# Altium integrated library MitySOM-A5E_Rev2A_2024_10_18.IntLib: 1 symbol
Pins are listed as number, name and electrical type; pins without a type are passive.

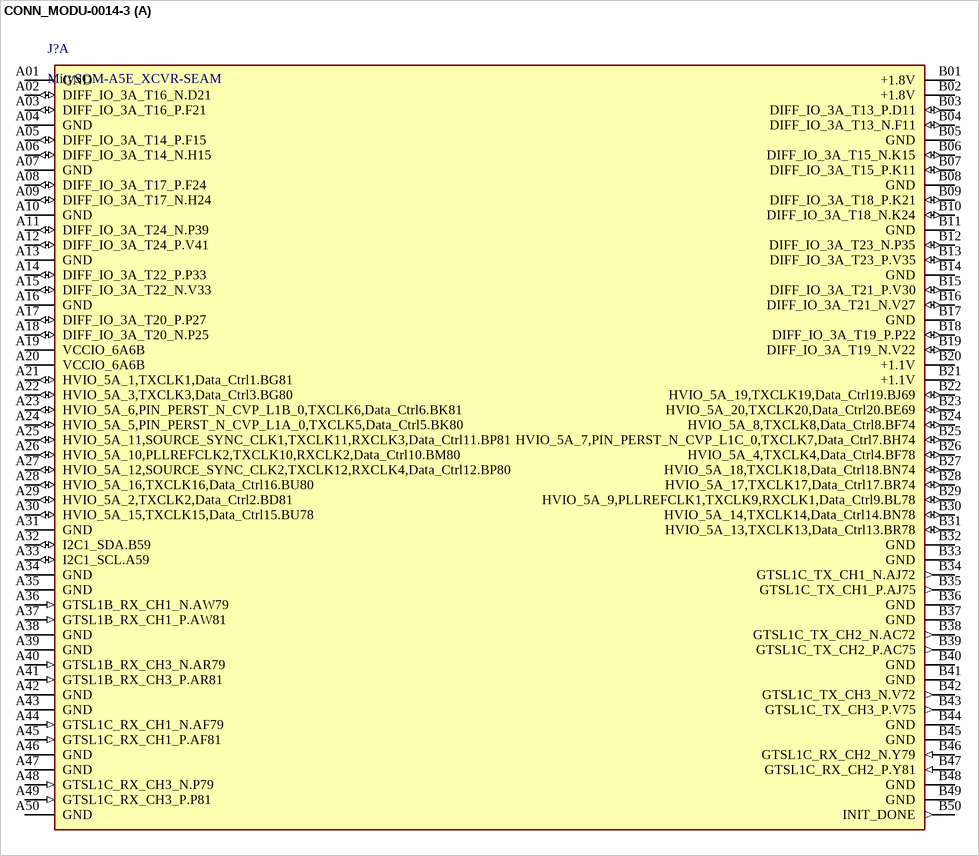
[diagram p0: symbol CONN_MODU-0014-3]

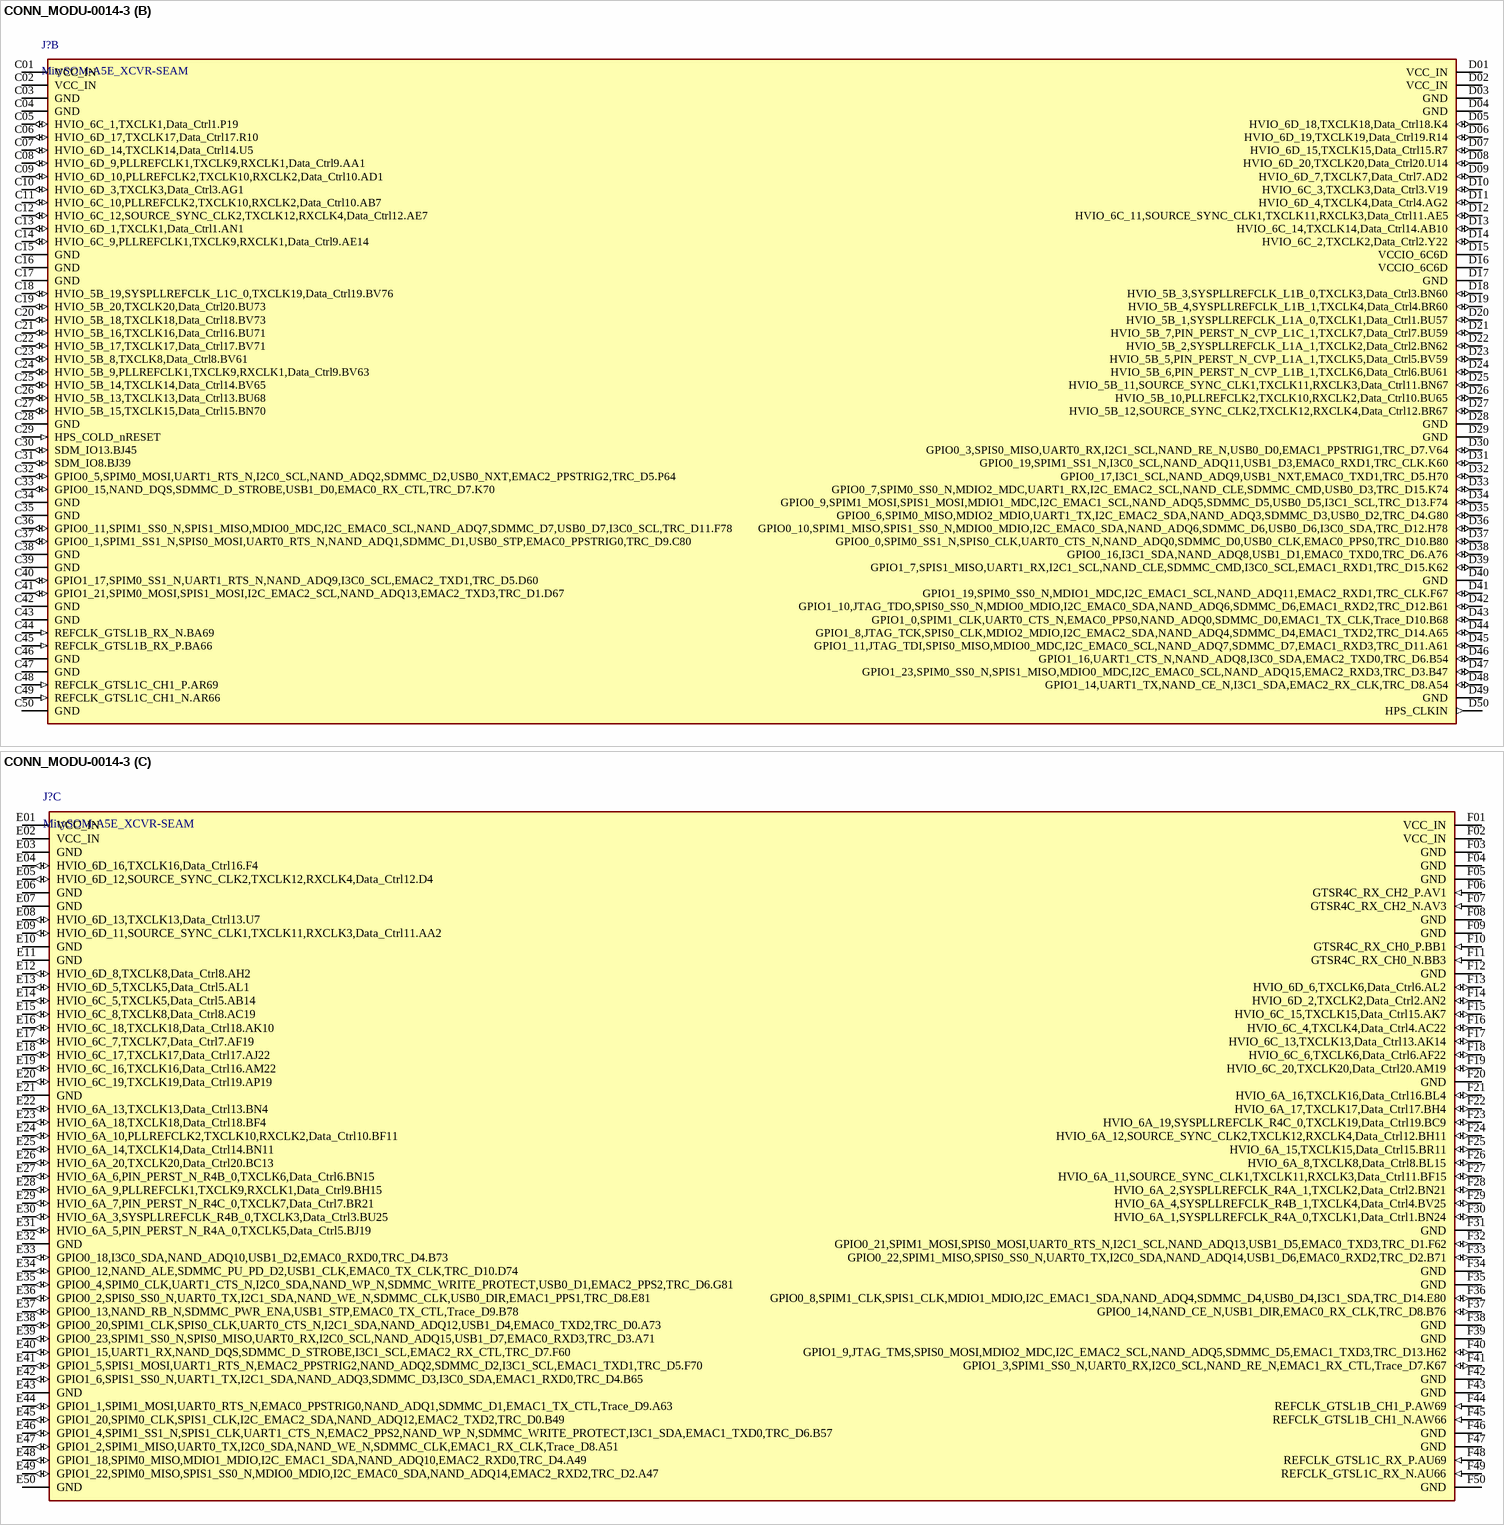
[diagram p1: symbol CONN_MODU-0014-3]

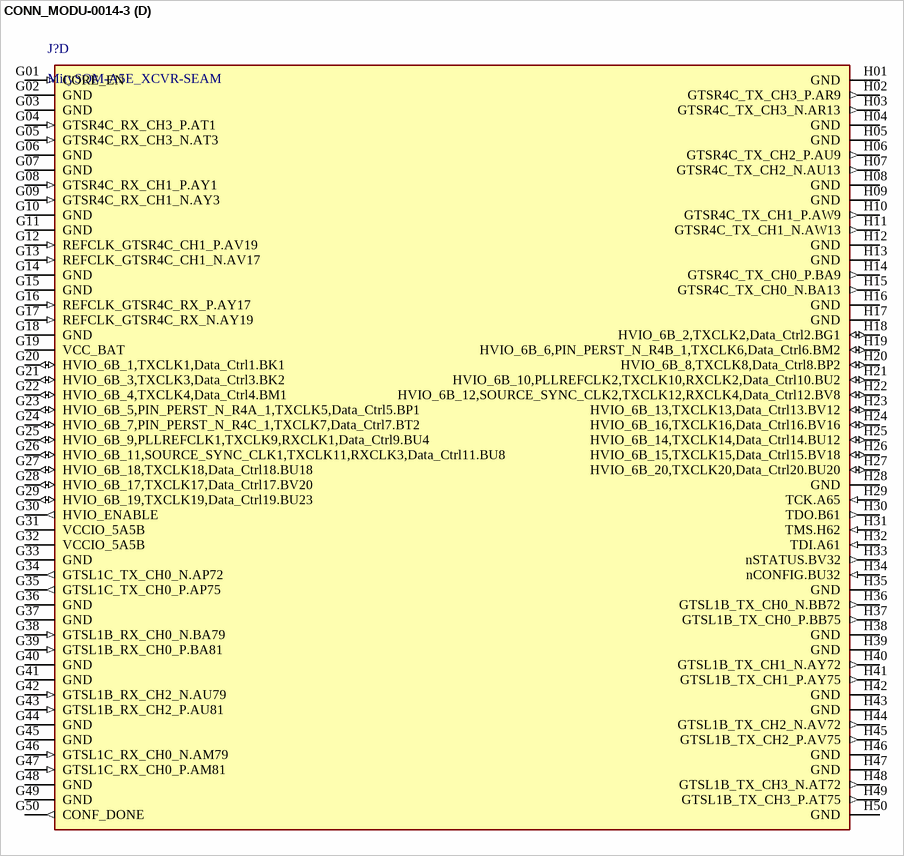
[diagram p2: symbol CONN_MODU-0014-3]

## CONN_MODU-0014-3
designator J?, comment MitySOM-A5E_XCVR-SEAM
MitySOM-A5E XCVR Interface Connector; Manuf 1_PN: SEAM-50-02.0-S-08-2-A-K-TR; Manuf 1: Samtec; CLPN: 13059; Angle: Vertical
footprint SEAM-50-02.0-S-08-2-A-K-TR (CONN ARRAY SOCKET 400 POS SMD)
part A pins: A01 GND (power), A02 DIFF_IO_3A_T16_N.D21 (io), A03 DIFF_IO_3A_T16_P.F21 (io), A04 GND (power), A05 DIFF_IO_3A_T14_P.F15 (io), A06 DIFF_IO_3A_T14_N.H15 (io), A07 GND (power), A08 DIFF_IO_3A_T17_P.F24 (io), A09 DIFF_IO_3A_T17_N.H24 (io), A10 GND (power), A11 DIFF_IO_3A_T24_N.P39 (io), A12 DIFF_IO_3A_T24_P.V41 (io), A13 GND (power), A14 DIFF_IO_3A_T22_P.P33 (io), A15 DIFF_IO_3A_T22_N.V33 (io), A16 GND (power), A17 DIFF_IO_3A_T20_P.P27 (io), A18 DIFF_IO_3A_T20_N.P25 (io), A19 VCCIO_6A6B (power), A20 VCCIO_6A6B (power), A21 HVIO_5A_1,TXCLK1,Data_Ctrl1.BG81 (io), A22 HVIO_5A_3,TXCLK3,Data_Ctrl3.BG80 (io), A23 HVIO_5A_6,PIN_PERST_N_CVP_L1B_0,TXCLK6,Data_Ctrl6.BK81 (io), A24 HVIO_5A_5,PIN_PERST_N_CVP_L1A_0,TXCLK5,Data_Ctrl5.BK80 (io), A25 HVIO_5A_11,SOURCE_SYNC_CLK1,TXCLK11,RXCLK3,Data_Ctrl11.BP81 (io), A26 HVIO_5A_10,PLLREFCLK2,TXCLK10,RXCLK2,Data_Ctrl10.BM80 (io), A27 HVIO_5A_12,SOURCE_SYNC_CLK2,TXCLK12,RXCLK4,Data_Ctrl12.BP80 (io), A28 HVIO_5A_16,TXCLK16,Data_Ctrl16.BU80 (io), A29 HVIO_5A_2,TXCLK2,Data_Ctrl2.BD81 (io), A30 HVIO_5A_15,TXCLK15,Data_Ctrl15.BU78 (io), A31 GND (power), A32 I2C1_SDA.B59 (io), A33 I2C1_SCL.A59 (io), A34 GND (power), A35 GND (power), A36 GTSL1B_RX_CH1_N.AW79 (in), A37 GTSL1B_RX_CH1_P.AW81 (in), A38 GND (power), A39 GND (power), A40 GTSL1B_RX_CH3_N.AR79 (in), A41 GTSL1B_RX_CH3_P.AR81 (in), A42 GND (power), A43 GND (power), A44 GTSL1C_RX_CH1_N.AF79 (in), A45 GTSL1C_RX_CH1_P.AF81 (in), A46 GND (power), A47 GND (power), A48 GTSL1C_RX_CH3_N.P79 (in), A49 GTSL1C_RX_CH3_P.P81 (in), A50 GND (power), B01 +1.8V (power), B02 +1.8V (power), B03 DIFF_IO_3A_T13_P.D11 (io), B04 DIFF_IO_3A_T13_N.F11 (io), B05 GND (power), B06 DIFF_IO_3A_T15_N.K15 (io), B07 DIFF_IO_3A_T15_P.K11 (io), B08 GND (power), B09 DIFF_IO_3A_T18_P.K21 (io), B10 DIFF_IO_3A_T18_N.K24 (io), B11 GND (power), B12 DIFF_IO_3A_T23_N.P35 (io), B13 DIFF_IO_3A_T23_P.V35 (io), B14 GND (power), B15 DIFF_IO_3A_T21_P.V30 (io), B16 DIFF_IO_3A_T21_N.V27 (io), B17 GND (power), B18 DIFF_IO_3A_T19_P.P22 (io), B19 DIFF_IO_3A_T19_N.V22 (io), B20 +1.1V (power), B21 +1.1V (power), B22 HVIO_5A_19,TXCLK19,Data_Ctrl19.BJ69 (io), B23 HVIO_5A_20,TXCLK20,Data_Ctrl20.BE69 (io), B24 HVIO_5A_8,TXCLK8,Data_Ctrl8.BF74 (io), B25 HVIO_5A_7,PIN_PERST_N_CVP_L1C_0,TXCLK7,Data_Ctrl7.BH74 (io), B26 HVIO_5A_4,TXCLK4,Data_Ctrl4.BF78 (io), B27 HVIO_5A_18,TXCLK18,Data_Ctrl18.BN74 (io), B28 HVIO_5A_17,TXCLK17,Data_Ctrl17.BR74 (io), B29 HVIO_5A_9,PLLREFCLK1,TXCLK9,RXCLK1,Data_Ctrl9.BL78 (io), B30 HVIO_5A_14,TXCLK14,Data_Ctrl14.BN78 (io), B31 HVIO_5A_13,TXCLK13,Data_Ctrl13.BR78 (io), B32 GND (power), B33 GND (power), B34 GTSL1C_TX_CH1_N.AJ72 (out), B35 GTSL1C_TX_CH1_P.AJ75 (out), B36 GND (power), B37 GND (power), B38 GTSL1C_TX_CH2_N.AC72 (out), B39 GTSL1C_TX_CH2_P.AC75 (out), B40 GND (power), B41 GND (power), B42 GTSL1C_TX_CH3_N.V72 (out), B43 GTSL1C_TX_CH3_P.V75 (out), B44 GND (power), B45 GND (power), B46 GTSL1C_RX_CH2_N.Y79 (in), B47 GTSL1C_RX_CH2_P.Y81 (in), B48 GND (power), B49 GND (power), B50 INIT_DONE (out)
part B pins: C01 VCC_IN (power), C02 VCC_IN (power), C03 GND (power), C04 GND (power), C05 HVIO_6C_1,TXCLK1,Data_Ctrl1.P19 (io), C06 HVIO_6D_17,TXCLK17,Data_Ctrl17.R10 (io), C07 HVIO_6D_14,TXCLK14,Data_Ctrl14.U5 (io), C08 HVIO_6D_9,PLLREFCLK1,TXCLK9,RXCLK1,Data_Ctrl9.AA1 (io), C09 HVIO_6D_10,PLLREFCLK2,TXCLK10,RXCLK2,Data_Ctrl10.AD1 (io), C10 HVIO_6D_3,TXCLK3,Data_Ctrl3.AG1 (io), C11 HVIO_6C_10,PLLREFCLK2,TXCLK10,RXCLK2,Data_Ctrl10.AB7 (io), C12 HVIO_6C_12,SOURCE_SYNC_CLK2,TXCLK12,RXCLK4,Data_Ctrl12.AE7 (io), C13 HVIO_6D_1,TXCLK1,Data_Ctrl1.AN1 (io), C14 HVIO_6C_9,PLLREFCLK1,TXCLK9,RXCLK1,Data_Ctrl9.AE14 (io), C15 GND (power), C16 GND (power), C17 GND (power), C18 HVIO_5B_19,SYSPLLREFCLK_L1C_0,TXCLK19,Data_Ctrl19.BV76 (io), C19 HVIO_5B_20,TXCLK20,Data_Ctrl20.BU73 (io), C20 HVIO_5B_18,TXCLK18,Data_Ctrl18.BV73 (io), C21 HVIO_5B_16,TXCLK16,Data_Ctrl16.BU71 (io), C22 HVIO_5B_17,TXCLK17,Data_Ctrl17.BV71 (io), C23 HVIO_5B_8,TXCLK8,Data_Ctrl8.BV61 (io), C24 HVIO_5B_9,PLLREFCLK1,TXCLK9,RXCLK1,Data_Ctrl9.BV63 (io), C25 HVIO_5B_14,TXCLK14,Data_Ctrl14.BV65 (io), C26 HVIO_5B_13,TXCLK13,Data_Ctrl13.BU68 (io), C27 HVIO_5B_15,TXCLK15,Data_Ctrl15.BN70 (io), C28 GND (power), C29 HPS_COLD_nRESET (in), C30 SDM_IO13.BJ45 (io), C31 SDM_IO8.BJ39 (io), C32 GPIO0_5,SPIM0_MOSI,UART1_RTS_N,I2C0_SCL,NAND_ADQ2,SDMMC_D2,USB0_NXT,EMAC2_PPSTRIG2,TRC_D5.P64 (io), C33 GPIO0_15,NAND_DQS,SDMMC_D_STROBE,USB1_D0,EMAC0_RX_CTL,TRC_D7.K70 (io), C34 GND (power), C35 GND (power), C36 GPIO0_11,SPIM1_SS0_N,SPIS1_MISO,MDIO0_MDC,I2C_EMAC0_SCL,NAND_ADQ7,SDMMC_D7,USB0_D7,I3C0_SCL,TRC_D11.F78 (io), C37 GPIO0_1,SPIM1_SS1_N,SPIS0_MOSI,UART0_RTS_N,NAND_ADQ1,SDMMC_D1,USB0_STP,EMAC0_PPSTRIG0,TRC_D9.C80 (io), C38 GND (power), C39 GND (power), C40 GPIO1_17,SPIM0_SS1_N,UART1_RTS_N,NAND_ADQ9,I3C0_SCL,EMAC2_TXD1,TRC_D5.D60 (io), C41 GPIO1_21,SPIM0_MOSI,SPIS1_MOSI,I2C_EMAC2_SCL,NAND_ADQ13,EMAC2_TXD3,TRC_D1.D67 (io), C42 GND (power), C43 GND (power), C44 REFCLK_GTSL1B_RX_N.BA69 (in), C45 REFCLK_GTSL1B_RX_P.BA66 (in), C46 GND (power), C47 GND (power), C48 REFCLK_GTSL1C_CH1_P.AR69 (in), C49 REFCLK_GTSL1C_CH1_N.AR66 (in), C50 GND (power), D01 VCC_IN (power), D02 VCC_IN (power), D03 GND (power), D04 GND (power), D05 HVIO_6D_18,TXCLK18,Data_Ctrl18.K4 (io), D06 HVIO_6D_19,TXCLK19,Data_Ctrl19.R14 (io), D07 HVIO_6D_15,TXCLK15,Data_Ctrl15.R7 (io), D08 HVIO_6D_20,TXCLK20,Data_Ctrl20.U14 (io), D09 HVIO_6D_7,TXCLK7,Data_Ctrl7.AD2 (io), D10 HVIO_6C_3,TXCLK3,Data_Ctrl3.V19 (io), D11 HVIO_6D_4,TXCLK4,Data_Ctrl4.AG2 (io), D12 HVIO_6C_11,SOURCE_SYNC_CLK1,TXCLK11,RXCLK3,Data_Ctrl11.AE5 (io), D13 HVIO_6C_14,TXCLK14,Data_Ctrl14.AB10 (io), D14 HVIO_6C_2,TXCLK2,Data_Ctrl2.Y22 (io), D15 VCCIO_6C6D (power), D16 VCCIO_6C6D (power), D17 GND (power), D18 HVIO_5B_3,SYSPLLREFCLK_L1B_0,TXCLK3,Data_Ctrl3.BN60 (io), D19 HVIO_5B_4,SYSPLLREFCLK_L1B_1,TXCLK4,Data_Ctrl4.BR60 (io), D20 HVIO_5B_1,SYSPLLREFCLK_L1A_0,TXCLK1,Data_Ctrl1.BU57 (io), D21 HVIO_5B_7,PIN_PERST_N_CVP_L1C_1,TXCLK7,Data_Ctrl7.BU59 (io), D22 HVIO_5B_2,SYSPLLREFCLK_L1A_1,TXCLK2,Data_Ctrl2.BN62 (io), D23 HVIO_5B_5,PIN_PERST_N_CVP_L1A_1,TXCLK5,Data_Ctrl5.BV59 (io), D24 HVIO_5B_6,PIN_PERST_N_CVP_L1B_1,TXCLK6,Data_Ctrl6.BU61 (io), D25 HVIO_5B_11,SOURCE_SYNC_CLK1,TXCLK11,RXCLK3,Data_Ctrl11.BN67 (io), D26 HVIO_5B_10,PLLREFCLK2,TXCLK10,RXCLK2,Data_Ctrl10.BU65 (io), D27 HVIO_5B_12,SOURCE_SYNC_CLK2,TXCLK12,RXCLK4,Data_Ctrl12.BR67 (io), D28 GND (power), D29 GND (power), D30 GPIO0_3,SPIS0_MISO,UART0_RX,I2C1_SCL,NAND_RE_N,USB0_D0,EMAC1_PPSTRIG1,TRC_D7.V64 (io), D31 GPIO0_19,SPIM1_SS1_N,I3C0_SCL,NAND_ADQ11,USB1_D3,EMAC0_RXD1,TRC_CLK.K60 (io), D32 GPIO0_17,I3C1_SCL,NAND_ADQ9,USB1_NXT,EMAC0_TXD1,TRC_D5.H70 (io), D33 GPIO0_7,SPIM0_SS0_N,MDIO2_MDC,UART1_RX,I2C_EMAC2_SCL,NAND_CLE,SDMMC_CMD,USB0_D3,TRC_D15.K74 (io), D34 GPIO0_9,SPIM1_MOSI,SPIS1_MOSI,MDIO1_MDC,I2C_EMAC1_SCL,NAND_ADQ5,SDMMC_D5,USB0_D5,I3C1_SCL,TRC_D13.F74 (io), D35 GPIO0_6,SPIM0_MISO,MDIO2_MDIO,UART1_TX,I2C_EMAC2_SDA,NAND_ADQ3,SDMMC_D3,USB0_D2,TRC_D4.G80 (io), D36 GPIO0_10,SPIM1_MISO,SPIS1_SS0_N,MDIO0_MDIO,I2C_EMAC0_SDA,NAND_ADQ6,SDMMC_D6,USB0_D6,I3C0_SDA,TRC_D12.H78 (io), D37 GPIO0_0,SPIM0_SS1_N,SPIS0_CLK,UART0_CTS_N,NAND_ADQ0,SDMMC_D0,USB0_CLK,EMAC0_PPS0,TRC_D10.B80 (io), D38 GPIO0_16,I3C1_SDA,NAND_ADQ8,USB1_D1,EMAC0_TXD0,TRC_D6.A76 (io), D39 GPIO1_7,SPIS1_MISO,UART1_RX,I2C1_SCL,NAND_CLE,SDMMC_CMD,I3C0_SCL,EMAC1_RXD1,TRC_D15.K62 (io), D40 GND (power), D41 GPIO1_19,SPIM0_SS0_N,MDIO1_MDC,I2C_EMAC1_SCL,NAND_ADQ11,EMAC2_RXD1,TRC_CLK.F67 (io), D42 GPIO1_10,JTAG_TDO,SPIS0_SS0_N,MDIO0_MDIO,I2C_EMAC0_SDA,NAND_ADQ6,SDMMC_D6,EMAC1_RXD2,TRC_D12.B61 (io), D43 GPIO1_0,SPIM1_CLK,UART0_CTS_N,EMAC0_PPS0,NAND_ADQ0,SDMMC_D0,EMAC1_TX_CLK,Trace_D10.B68 (io), D44 GPIO1_8,JTAG_TCK,SPIS0_CLK,MDIO2_MDIO,I2C_EMAC2_SDA,NAND_ADQ4,SDMMC_D4,EMAC1_TXD2,TRC_D14.A65 (io), D45 GPIO1_11,JTAG_TDI,SPIS0_MISO,MDIO0_MDC,I2C_EMAC0_SCL,NAND_ADQ7,SDMMC_D7,EMAC1_RXD3,TRC_D11.A61 (io), D46 GPIO1_16,UART1_CTS_N,NAND_ADQ8,I3C0_SDA,EMAC2_TXD0,TRC_D6.B54 (io), D47 GPIO1_23,SPIM0_SS0_N,SPIS1_MISO,MDIO0_MDC,I2C_EMAC0_SCL,NAND_ADQ15,EMAC2_RXD3,TRC_D3.B47 (io), D48 GPIO1_14,UART1_TX,NAND_CE_N,I3C1_SDA,EMAC2_RX_CLK,TRC_D8.A54 (io), D49 GND (power), D50 HPS_CLKIN (out)
part C pins: E01 VCC_IN (power), E02 VCC_IN (power), E03 GND (power), E04 HVIO_6D_16,TXCLK16,Data_Ctrl16.F4 (io), E05 HVIO_6D_12,SOURCE_SYNC_CLK2,TXCLK12,RXCLK4,Data_Ctrl12.D4 (io), E06 GND (power), E07 GND (power), E08 HVIO_6D_13,TXCLK13,Data_Ctrl13.U7 (io), E09 HVIO_6D_11,SOURCE_SYNC_CLK1,TXCLK11,RXCLK3,Data_Ctrl11.AA2 (io), E10 GND (power), E11 GND (power), E12 HVIO_6D_8,TXCLK8,Data_Ctrl8.AH2 (io), E13 HVIO_6D_5,TXCLK5,Data_Ctrl5.AL1 (io), E14 HVIO_6C_5,TXCLK5,Data_Ctrl5.AB14 (io), E15 HVIO_6C_8,TXCLK8,Data_Ctrl8.AC19 (io), E16 HVIO_6C_18,TXCLK18,Data_Ctrl18.AK10 (io), E17 HVIO_6C_7,TXCLK7,Data_Ctrl7.AF19 (io), E18 HVIO_6C_17,TXCLK17,Data_Ctrl17.AJ22 (io), E19 HVIO_6C_16,TXCLK16,Data_Ctrl16.AM22 (io), E20 HVIO_6C_19,TXCLK19,Data_Ctrl19.AP19 (io), E21 GND (power), E22 HVIO_6A_13,TXCLK13,Data_Ctrl13.BN4 (io), E23 HVIO_6A_18,TXCLK18,Data_Ctrl18.BF4 (io), E24 HVIO_6A_10,PLLREFCLK2,TXCLK10,RXCLK2,Data_Ctrl10.BF11 (io), E25 HVIO_6A_14,TXCLK14,Data_Ctrl14.BN11 (io), E26 HVIO_6A_20,TXCLK20,Data_Ctrl20.BC13 (io), E27 HVIO_6A_6,PIN_PERST_N_R4B_0,TXCLK6,Data_Ctrl6.BN15 (io), E28 HVIO_6A_9,PLLREFCLK1,TXCLK9,RXCLK1,Data_Ctrl9.BH15 (io), E29 HVIO_6A_7,PIN_PERST_N_R4C_0,TXCLK7,Data_Ctrl7.BR21 (io), E30 HVIO_6A_3,SYSPLLREFCLK_R4B_0,TXCLK3,Data_Ctrl3.BU25 (io), E31 HVIO_6A_5,PIN_PERST_N_R4A_0,TXCLK5,Data_Ctrl5.BJ19 (io), E32 GND (power), E33 GPIO0_18,I3C0_SDA,NAND_ADQ10,USB1_D2,EMAC0_RXD0,TRC_D4.B73 (io), E34 GPIO0_12,NAND_ALE,SDMMC_PU_PD_D2,USB1_CLK,EMAC0_TX_CLK,TRC_D10.D74 (io), E35 GPIO0_4,SPIM0_CLK,UART1_CTS_N,I2C0_SDA,NAND_WP_N,SDMMC_WRITE_PROTECT,USB0_D1,EMAC2_PPS2,TRC_D6.G81 (io), E36 GPIO0_2,SPIS0_SS0_N,UART0_TX,I2C1_SDA,NAND_WE_N,SDMMC_CLK,USB0_DIR,EMAC1_PPS1,TRC_D8.E81 (io), E37 GPIO0_13,NAND_RB_N,SDMMC_PWR_ENA,USB1_STP,EMAC0_TX_CTL,Trace_D9.B78 (io), E38 GPIO0_20,SPIM1_CLK,SPIS0_CLK,UART0_CTS_N,I2C1_SDA,NAND_ADQ12,USB1_D4,EMAC0_TXD2,TRC_D0.A73 (io), E39 GPIO0_23,SPIM1_SS0_N,SPIS0_MISO,UART0_RX,I2C0_SCL,NAND_ADQ15,USB1_D7,EMAC0_RXD3,TRC_D3.A71 (io), E40 GPIO1_15,UART1_RX,NAND_DQS,SDMMC_D_STROBE,I3C1_SCL,EMAC2_RX_CTL,TRC_D7.F60 (io), E41 GPIO1_5,SPIS1_MOSI,UART1_RTS_N,EMAC2_PPSTRIG2,NAND_ADQ2,SDMMC_D2,I3C1_SCL,EMAC1_TXD1,TRC_D5.F70 (io), E42 GPIO1_6,SPIS1_SS0_N,UART1_TX,I2C1_SDA,NAND_ADQ3,SDMMC_D3,I3C0_SDA,EMAC1_RXD0,TRC_D4.B65 (io), E43 GND (power), E44 GPIO1_1,SPIM1_MOSI,UART0_RTS_N,EMAC0_PPSTRIG0,NAND_ADQ1,SDMMC_D1,EMAC1_TX_CTL,Trace_D9.A63 (io), E45 GPIO1_20,SPIM0_CLK,SPIS1_CLK,I2C_EMAC2_SDA,NAND_ADQ12,EMAC2_TXD2,TRC_D0.B49 (io), E46 GPIO1_4,SPIM1_SS1_N,SPIS1_CLK,UART1_CTS_N,EMAC2_PPS2,NAND_WP_N,SDMMC_WRITE_PROTECT,I3C1_SDA,EMAC1_TXD0,TRC_D6.B57 (io), E47 GPIO1_2,SPIM1_MISO,UART0_TX,I2C0_SDA,NAND_WE_N,SDMMC_CLK,EMAC1_RX_CLK,Trace_D8.A51 (io), E48 GPIO1_18,SPIM0_MISO,MDIO1_MDIO,I2C_EMAC1_SDA,NAND_ADQ10,EMAC2_RXD0,TRC_D4.A49 (io), E49 GPIO1_22,SPIM0_MISO,SPIS1_SS0_N,MDIO0_MDIO,I2C_EMAC0_SDA,NAND_ADQ14,EMAC2_RXD2,TRC_D2.A47 (io), E50 GND (power), F01 VCC_IN (power), F02 VCC_IN (power), F03 GND (power), F04 GND (power), F05 GND (power), F06 GTSR4C_RX_CH2_P.AV1 (in), F07 GTSR4C_RX_CH2_N.AV3 (in), F08 GND (power), F09 GND (power), F10 GTSR4C_RX_CH0_P.BB1 (in), F11 GTSR4C_RX_CH0_N.BB3 (in), F12 GND (power), F13 HVIO_6D_6,TXCLK6,Data_Ctrl6.AL2 (io), F14 HVIO_6D_2,TXCLK2,Data_Ctrl2.AN2 (io), F15 HVIO_6C_15,TXCLK15,Data_Ctrl15.AK7 (io), F16 HVIO_6C_4,TXCLK4,Data_Ctrl4.AC22 (io), F17 HVIO_6C_13,TXCLK13,Data_Ctrl13.AK14 (io), F18 HVIO_6C_6,TXCLK6,Data_Ctrl6.AF22 (io), F19 HVIO_6C_20,TXCLK20,Data_Ctrl20.AM19 (io), F20 GND (power), F21 HVIO_6A_16,TXCLK16,Data_Ctrl16.BL4 (io), F22 HVIO_6A_17,TXCLK17,Data_Ctrl17.BH4 (io), F23 HVIO_6A_19,SYSPLLREFCLK_R4C_0,TXCLK19,Data_Ctrl19.BC9 (io), F24 HVIO_6A_12,SOURCE_SYNC_CLK2,TXCLK12,RXCLK4,Data_Ctrl12.BH11 (io), F25 HVIO_6A_15,TXCLK15,Data_Ctrl15.BR11 (io), F26 HVIO_6A_8,TXCLK8,Data_Ctrl8.BL15 (io), F27 HVIO_6A_11,SOURCE_SYNC_CLK1,TXCLK11,RXCLK3,Data_Ctrl11.BF15 (io), F28 HVIO_6A_2,SYSPLLREFCLK_R4A_1,TXCLK2,Data_Ctrl2.BN21 (io), F29 HVIO_6A_4,SYSPLLREFCLK_R4B_1,TXCLK4,Data_Ctrl4.BV25 (io), F30 HVIO_6A_1,SYSPLLREFCLK_R4A_0,TXCLK1,Data_Ctrl1.BN24 (io), F31 GND (power), F32 GPIO0_21,SPIM1_MOSI,SPIS0_MOSI,UART0_RTS_N,I2C1_SCL,NAND_ADQ13,USB1_D5,EMAC0_TXD3,TRC_D1.F62 (io), F33 GPIO0_22,SPIM1_MISO,SPIS0_SS0_N,UART0_TX,I2C0_SDA,NAND_ADQ14,USB1_D6,EMAC0_RXD2,TRC_D2.B71 (io), F34 GND (power), F35 GND (power), F36 GPIO0_8,SPIM1_CLK,SPIS1_CLK,MDIO1_MDIO,I2C_EMAC1_SDA,NAND_ADQ4,SDMMC_D4,USB0_D4,I3C1_SDA,TRC_D14.E80 (io), F37 GPIO0_14,NAND_CE_N,USB1_DIR,EMAC0_RX_CLK,TRC_D8.B76 (io), F38 GND (power), F39 GND (power), F40 GPIO1_9,JTAG_TMS,SPIS0_MOSI,MDIO2_MDC,I2C_EMAC2_SCL,NAND_ADQ5,SDMMC_D5,EMAC1_TXD3,TRC_D13.H62 (io), F41 GPIO1_3,SPIM1_SS0_N,UART0_RX,I2C0_SCL,NAND_RE_N,EMAC1_RX_CTL,Trace_D7.K67 (io), F42 GND (power), F43 GND (power), F44 REFCLK_GTSL1B_CH1_P.AW69 (in), F45 REFCLK_GTSL1B_CH1_N.AW66 (in), F46 GND (power), F47 GND (power), F48 REFCLK_GTSL1C_RX_P.AU69 (in), F49 REFCLK_GTSL1C_RX_N.AU66 (in), F50 GND (power)
part D pins: G01 CORE_EN (in), G02 GND (power), G03 GND (power), G04 GTSR4C_RX_CH3_P.AT1 (in), G05 GTSR4C_RX_CH3_N.AT3 (in), G06 GND (power), G07 GND (power), G08 GTSR4C_RX_CH1_P.AY1 (in), G09 GTSR4C_RX_CH1_N.AY3 (in), G10 GND (power), G11 GND (power), G12 REFCLK_GTSR4C_CH1_P.AV19 (in), G13 REFCLK_GTSR4C_CH1_N.AV17 (in), G14 GND (power), G15 GND (power), G16 REFCLK_GTSR4C_RX_P.AY17 (in), G17 REFCLK_GTSR4C_RX_N.AY19 (in), G18 GND (power), G19 VCC_BAT (power), G20 HVIO_6B_1,TXCLK1,Data_Ctrl1.BK1 (io), G21 HVIO_6B_3,TXCLK3,Data_Ctrl3.BK2 (io), G22 HVIO_6B_4,TXCLK4,Data_Ctrl4.BM1 (io), G23 HVIO_6B_5,PIN_PERST_N_R4A_1,TXCLK5,Data_Ctrl5.BP1 (io), G24 HVIO_6B_7,PIN_PERST_N_R4C_1,TXCLK7,Data_Ctrl7.BT2 (io), G25 HVIO_6B_9,PLLREFCLK1,TXCLK9,RXCLK1,Data_Ctrl9.BU4 (io), G26 HVIO_6B_11,SOURCE_SYNC_CLK1,TXCLK11,RXCLK3,Data_Ctrl11.BU8 (io), G27 HVIO_6B_18,TXCLK18,Data_Ctrl18.BU18 (io), G28 HVIO_6B_17,TXCLK17,Data_Ctrl17.BV20 (io), G29 HVIO_6B_19,TXCLK19,Data_Ctrl19.BU23 (io), G30 HVIO_ENABLE (out), G31 VCCIO_5A5B (power), G32 VCCIO_5A5B (power), G33 GND (power), G34 GTSL1C_TX_CH0_N.AP72 (out), G35 GTSL1C_TX_CH0_P.AP75 (out), G36 GND (power), G37 GND (power), G38 GTSL1B_RX_CH0_N.BA79 (in), G39 GTSL1B_RX_CH0_P.BA81 (in), G40 GND (power), G41 GND (power), G42 GTSL1B_RX_CH2_N.AU79 (in), G43 GTSL1B_RX_CH2_P.AU81 (in), G44 GND (power), G45 GND (power), G46 GTSL1C_RX_CH0_N.AM79 (in), G47 GTSL1C_RX_CH0_P.AM81 (in), G48 GND (power), G49 GND (power), G50 CONF_DONE (out), H01 GND (power), H02 GTSR4C_TX_CH3_P.AR9 (out), H03 GTSR4C_TX_CH3_N.AR13 (out), H04 GND (power), H05 GND (power), H06 GTSR4C_TX_CH2_P.AU9 (out), H07 GTSR4C_TX_CH2_N.AU13 (out), H08 GND (power), H09 GND (power), H10 GTSR4C_TX_CH1_P.AW9 (out), H11 GTSR4C_TX_CH1_N.AW13 (out), H12 GND (power), H13 GND (power), H14 GTSR4C_TX_CH0_P.BA9 (out), H15 GTSR4C_TX_CH0_N.BA13 (out), H16 GND (power), H17 GND (power), H18 HVIO_6B_2,TXCLK2,Data_Ctrl2.BG1 (io), H19 HVIO_6B_6,PIN_PERST_N_R4B_1,TXCLK6,Data_Ctrl6.BM2 (io), H20 HVIO_6B_8,TXCLK8,Data_Ctrl8.BP2 (io), H21 HVIO_6B_10,PLLREFCLK2,TXCLK10,RXCLK2,Data_Ctrl10.BU2 (io), H22 HVIO_6B_12,SOURCE_SYNC_CLK2,TXCLK12,RXCLK4,Data_Ctrl12.BV8 (io), H23 HVIO_6B_13,TXCLK13,Data_Ctrl13.BV12 (io), H24 HVIO_6B_16,TXCLK16,Data_Ctrl16.BV16 (io), H25 HVIO_6B_14,TXCLK14,Data_Ctrl14.BU12 (io), H26 HVIO_6B_15,TXCLK15,Data_Ctrl15.BV18 (io), H27 HVIO_6B_20,TXCLK20,Data_Ctrl20.BU20 (io), H28 GND (power), H29 TCK.A65 (in), H30 TDO.B61 (out), H31 TMS.H62 (in), H32 TDI.A61 (in), H33 nSTATUS.BV32 (out), H34 nCONFIG.BU32 (in), H35 GND (power), H36 GTSL1B_TX_CH0_N.BB72 (out), H37 GTSL1B_TX_CH0_P.BB75 (out), H38 GND (power), H39 GND (power), H40 GTSL1B_TX_CH1_N.AY72 (out), H41 GTSL1B_TX_CH1_P.AY75 (out), H42 GND (power), H43 GND (power), H44 GTSL1B_TX_CH2_N.AV72 (out), H45 GTSL1B_TX_CH2_P.AV75 (out), H46 GND (power), H47 GND (power), H48 GTSL1B_TX_CH3_N.AT72 (out), H49 GTSL1B_TX_CH3_P.AT75 (out), H50 GND (power)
